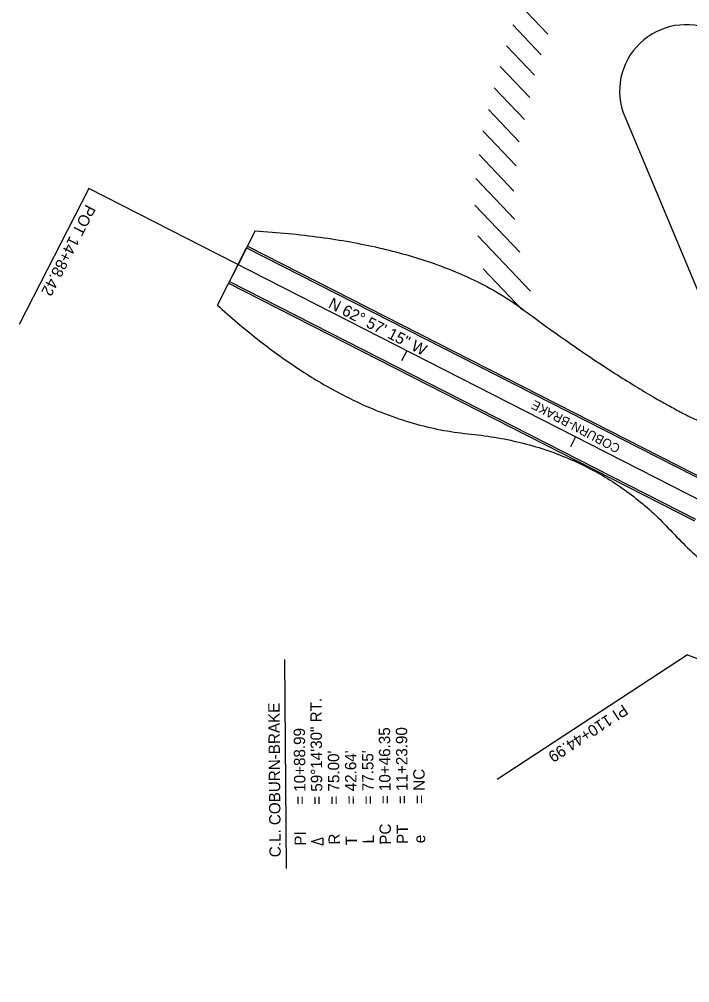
# Model space of a CAD drawing. Extents: x 1384823 to 1386442, y 1973842 to 1975611.
# Drawn here: x 1384823 to 1385177, y 1974216 to 1974725 of the extents above; entities that cross this region are included whole.
import ezdxf

# ---------------------------------------------------------------- set-up
doc = ezdxf.new("R2010")
doc.units = 0
for name, color, linetype in [('Default', 7, 'Continuous'), ('Level 6', 7, 'Continuous'), ('R_Draft', 7, 'Continuous'), ('R_Driveway', 7, 'Continuous'), ('R_Horz Alg', 7, 'Continuous'), ('R_Horz Alg Annot', 7, 'Continuous'), ('R_Horz Alg Stationing', 7, 'Continuous'), ('R_Prop Surface', 7, 'Continuous'), ('R_Proposed Const Limits', 7, 'Continuous'), ('R_Shld', 7, 'Continuous')]:
    doc.layers.add(name, color=color, linetype=linetype)

msp = doc.modelspace()

# ---------------------------------------------------------------- linework, layer by layer
at = {"layer": 'Level 6'}
msp.add_line((1384964.38, 1974276.38), (1384963.46, 1974386.71), dxfattribs=at)
msp.add_lwpolyline([(1384983.49, 1974288.67), (1384977.49, 1974290.6), (1384983.44, 1974292.58), (1384983.48, 1974288.67)], dxfattribs=at)
at = {"layer": 'R_Driveway'}
for p, q in [((1384934.21, 1974586.31), (1384943.3, 1974604.13)), ((1384943.3, 1974604.13), (1385189.21, 1974478.58)), ((1384934.21, 1974586.31), (1385180.12, 1974460.77))]:
    msp.add_line(p, q, dxfattribs=at)
at = {"layer": 'R_Horz Alg'}
msp.add_line((1385184.66, 1974469.67), (1384860, 1974635.42), dxfattribs=at)
at = {"layer": 'R_Horz Alg Annot'}
for p, q in [((1384860, 1974635.42), (1384823.34, 1974563.61)), ((1385175.93, 1974389.11), (1385645.53, 1974216.08))]:
    msp.add_line(p, q, dxfattribs=at)
msp.add_lwpolyline([(1385175.93, 1974389.11), (1385075.48, 1974323.46)], dxfattribs=at)
msp.add_lwpolyline([(1385175.93, 1974389.11), (1385075.48, 1974323.46)], dxfattribs=at)
at = {"layer": 'R_Horz Alg Stationing'}
for p, q in [((1384938.75, 1974595.22), (1384936.03, 1974589.88)), ((1385027.82, 1974549.75), (1385025.09, 1974544.41)), ((1385116.88, 1974504.28), (1385114.15, 1974498.93))]:
    msp.add_line(p, q, dxfattribs=at)
at = {"layer": 'R_Prop Surface'}
for p, q in [((1385102.26, 1974716.84), (1385087.32, 1974732.59)), ((1385098.74, 1974706.02), (1385083.84, 1974721.74)), ((1385095.23, 1974695.19), (1385080.42, 1974710.8)), ((1385092.64, 1974683.38), (1385077, 1974699.88)), ((1385089.9, 1974671.74), (1385073.97, 1974688.54)), ((1385087.16, 1974660.09), (1385070.95, 1974677.19)), ((1385085.5, 1974647.32), (1385067.93, 1974665.85)), ((1385084.33, 1974634.02), (1385065.95, 1974653.4)), ((1385084.81, 1974618.97), (1385064.16, 1974640.75)), ((1385087.37, 1974601.74), (1385063.78, 1974626.62)), ((1385093.05, 1974581.22), (1385065.32, 1974610.46)), ((1385088.86, 1974571.1), (1385068.1, 1974592.99))]:
    msp.add_line(p, q, dxfattribs=at)
at = {"layer": 'R_Proposed Const Limits'}
for p in [(1384947.85, 1974613.03), (1384927.84, 1974573.84)]:
    msp.add_line(p, (1384938.75, 1974595.22), dxfattribs=at)
msp.add_lwpolyline([(1385142.82, 1974673.34), (1385190.65, 1974559.09)], dxfattribs=at)
msp.add_arc((1385175.1, 1974686.86), 35, 65.2834, 202.7184, dxfattribs=at)
for points in [[(1384947.85, 1974613.03), (1385041.24, 1974607.26), (1385137.89, 1974535.23), (1385212.58, 1974496.45), (1385190.65, 1974559.09)], [(1384927.84, 1974573.84), (1384995.55, 1974512.2), (1385125.46, 1974499.52), (1385208.39, 1974410.41), (1385294.34, 1974363.68)]]:
    msp.add_open_spline(points, degree=2, dxfattribs=at)
at = {"layer": 'R_Shld'}
for p, q in [((1384943.76, 1974605.02), (1385189.66, 1974479.47)), ((1384933.75, 1974585.42), (1385179.66, 1974459.88))]:
    msp.add_line(p, q, dxfattribs=at)

# ---------------------------------------------------------------- texts
at = {"layer": 'Default'}
msp.add_text('N 62%%d 57\' 15" W', height=6, rotation=332.9542, dxfattribs=at).set_placement((1384985.92, 1974572.7))
at = {"layer": 'Level 6'}
for s, height, p in [('C.L. COBURN-BRAKE', 6.0001, (1384961.33, 1974282.36)), ('= 59%%D14\'30" RT.', 6.0001, (1384983.31, 1974310.06)), ('= 10+88.99', 6, (1384974.42, 1974309.99)), ('= 10+46.35', 6, (1385019.31, 1974310.36)), ('= 11+23.90', 6, (1385028.33, 1974310.44)), ("= 75.00'", 6, (1384992.33, 1974310.14)), ("= 42.64'", 6, (1385001.35, 1974310.26)), ("= 77.55'", 6, (1385010.37, 1974310.29)), ('= NC', 6, (1385037.35, 1974310.51)), ('PC', 6, (1385019.49, 1974288.97)), ('PT', 6, (1385028.51, 1974289.37)), ('PI', 6, (1384974.6, 1974288.47)), ('R', 6, (1384992.51, 1974289.07)), ('T', 6, (1385001.53, 1974288.74)), ('L', 6, (1385010.54, 1974289.62)), ('e', 6, (1385037.52, 1974289.76))]:
    msp.add_text(s, height=height, rotation=90.475, dxfattribs=at).set_placement(p)
at = {"layer": 'R_Draft'}
msp.add_text('COBURN-BRAKE', height=4.8, rotation=152.0972, dxfattribs=at).set_placement((1385140.9, 1974499.63))
at = {"layer": 'R_Horz Alg Annot'}
for s, rotation, p in [('POT 14+88.42', 242.9542, (1384858.58, 1974627.37)), ('PI 110+44.99', 213.1672, (1385141.94, 1974363.31))]:
    msp.add_text(s, height=6, rotation=rotation, dxfattribs=at).set_placement(p)

doc.saveas('drawing.dxf')
